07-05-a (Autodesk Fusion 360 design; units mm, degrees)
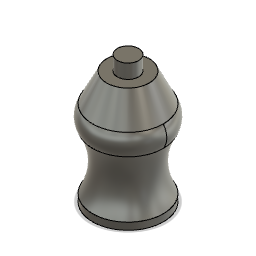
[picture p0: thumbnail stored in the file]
sketch "スケッチ1" plane through (0, 0, 0) normal (0, 1, 0) x axis (1, 0, 0)
  circle C1 centre (0, 0) radius 25
  point P1 (0, 0)
  point P2 (0, 0)
  coincident P1 P2
  dimension "d1" diameter C1 = 50
extrude "押し出し1" new body sketch "スケッチ1" along normal blind 5
work_plane "作業平面1" AlongDistance 20
sketch "スケッチ2" plane through (0, 25, 0) normal (0, 1, 0) x axis (1, 0, 0)
  circle C1 centre (0, 0) radius 20
  point P1 (0, 0)
  point P2 (0, 0)
  coincident P1 P2
  dimension "d5" diameter C1 = 40
work_plane "作業平面2" AlongDistance 20
sketch "スケッチ3" plane through (0, 45, 0) normal (0, 1, 0) x axis (1, 0, 0)
  circle C1 centre (0, 0) radius 25
loft "ロフト1" sketch "スケッチ2" + "スケッチ3"
work_plane "作業平面3" AlongDistance 15
sketch "スケッチ4" plane through (0, 60, 0) normal (0, 1, 0) x axis (1, 0, 0)
  circle C1 centre (0, 0) radius 25
sketch "スケッチ5" plane through (0, 0, 0) normal (0, 0, 1) x axis (1, 0, 0)
  line L1 (-25, 60) -> (25, 60)
  line L2 (25, 45) -> (-25, 45)
  arc A1 centre (-14.3816, 52.5) radius 13 clockwise from (-25, 45) to (-25, 60)
  arc A2 centre (14.3816, 52.5) radius 13 clockwise from (25, 60) to (25, 45)
  point P2 (-25, 60)
  point P9 (-25, 60)
  point P3 (-25, 45)
  point P10 (-25, 45)
  point P5 (25, 60)
  point P8 (25, 60)
  point P6 (25, 45)
  point P11 (25, 45)
  coincident P2 P9
  coincident P3 P10
  coincident P5 P8
  coincident P6 P11
  equal A1 A2
  dimension "d8" radius A1 = 13
sketch "スケッチ6" plane through (0, 0, 0) normal (1, 0, 0) x axis (0, 0, -1)
  line L1 (-25, 60) -> (25, 60)
  line L2 (25, 45) -> (-25, 45)
  arc A1 centre (-14.3816, 52.5) radius 13 clockwise from (-25, 45) to (-25, 60)
  arc A2 centre (14.3816, 52.5) radius 13 clockwise from (25, 60) to (25, 45)
  point P2 (-25, 60)
  point P9 (-25, 60)
  point P3 (-25, 45)
  point P10 (-25, 45)
  point P6 (25, 45)
  point P11 (25, 45)
  point P5 (25, 60)
  point P8 (25, 60)
  coincident P2 P9
  coincident P3 P10
  coincident P6 P11
  coincident P5 P8
  equal A1 A2
  dimension "d9" radius A1 = 13
loft "ロフト2" sketch "スケッチ4"
work_plane "作業平面4" AlongDistance 20
sketch "スケッチ7" plane through (0, 80, 0) normal (0, 1, 0) x axis (1, 0, 0)
  circle C1 centre (0, 0) radius 15
  point P1 (0, 0)
  point P2 (0, 0)
  coincident P1 P2
  dimension "d12" diameter C1 = 30
loft "ロフト3" sketch "スケッチ7"
sketch "スケッチ8" plane through (0, 80, 0) normal (0, 1, 0) x axis (-1, 0, 0)
  circle C1 centre (0, 0) radius 15
  circle C2 centre (0, 0) radius 7.5
  point P1 (0, 0)
  point P3 (0, 0)
  coincident P1 P3
  dimension "d13" diameter C2 = 15
extrude "押し出し2" add sketch "スケッチ8" profile of C2 along normal blind 10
